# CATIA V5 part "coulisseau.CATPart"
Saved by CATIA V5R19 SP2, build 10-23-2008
Part number: coulisseau
Publications: "Hcoulisseau", "Lcoulisseau"
Bounding box of the stored display mesh (mm): x -10 to 10, y -20 to 20, z -15 to 15
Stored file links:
  C:\Users\pierre\Documents\IFMA\IAO\coulisseau.CATPart
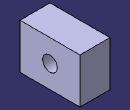
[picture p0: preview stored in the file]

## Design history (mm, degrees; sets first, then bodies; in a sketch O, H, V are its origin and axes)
Parameters
  Hcoulisseau = 30 mm
  Lcoulisseau = 40 mm
Body1 (main body)
  Point1: (0, 0, 0)
  Plane1: type Offset, RefPlane zx-plane, Offset 20 {= Lcoulisseau /2}
  Plane2: type Offset, RefPlane zx-plane, Offset 20 {= Lcoulisseau /2}, reversed
  Plane3: type Offset, RefPlane xy-plane, Offset 15 {= Hcoulisseau /2}
  Plane4: type Offset, RefPlane xy-plane, Offset 15 {= Hcoulisseau /2}, reversed
  Sketch1 on yz-plane, origin (0, 0, 0), H (0, 1, 0), V (0, 0, 1)
    line L1 (-20, 15) -> (20, 15)
    line L2 (20, 15) -> (20, -15)
    line L3 (20, -15) -> (-20, -15)
    line L4 (-20, -15) -> (-20, 15)
    reference intersected line E1 through (0, 15) direction (-1, 0) from Plane3
    reference intersected line E2 through (-20, 0) direction (0, 1) from Plane2
    reference intersected line E3 through (0, -15) direction (-1, 0) from Plane4
    reference intersected line E4 through (20, 0) direction (0, 1) from Plane1
    horizontal: L1 H, L3 H
    vertical: L2 V, L4 V
    coincidence: E1 L1, L4 E2, L3 E3, E4 L2
  Pad1: profile Sketch1, direction (1, 0, 0), length 10, mirrored extent
  Sketch2 on yz-plane, origin (0, 0, 0), H (0, 1, 0), V (0, 0, 1)
    point P1 (0, 0)
    reference projected point E1 (0, 0) from Point1
    coincidence: E1 P1
  Hole1: placed by Sketch2, at (0, 0, 0) direction (-1, 0, 0), diameter 10, through (limit type 6)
